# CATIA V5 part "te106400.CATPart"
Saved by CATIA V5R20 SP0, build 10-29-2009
Part number: 1
Definition: NONE
Nomenclature: 1
Source: Unknown
Description: PART-1-DESC
Bounding box of the stored display mesh (mm): x 0 to 400, y -5 to 5, z -5 to 5
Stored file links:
  C:\Users\Utente\Desktop\IO LAVORO\3D X SITO CF\CUMSA\3D files TE\te106400.CATPart
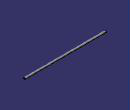
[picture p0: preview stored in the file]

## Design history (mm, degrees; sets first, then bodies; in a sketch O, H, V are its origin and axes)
Body1 "1" (main body)
  Solid1: solid without history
